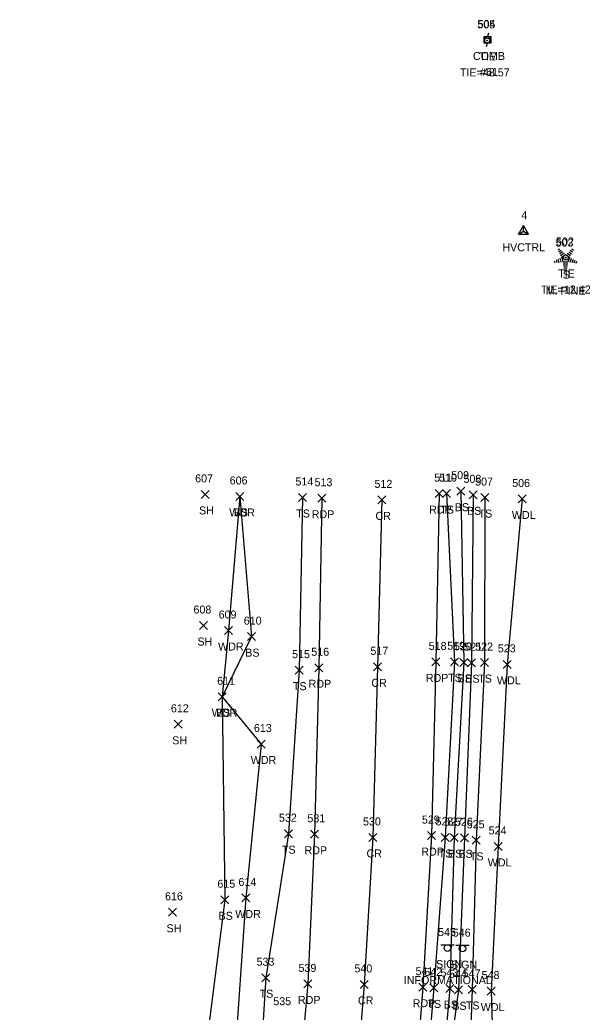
# Model space of a CAD drawing. Extents: x 1638705 to 1644019, y 630225 to 637423.
# Drawn here: x 1643810.7 to 1643953.1, y 637174.9 to 637422.9 of the extents above; entities that cross this region are included whole.
import ezdxf

# ---------------------------------------------------------------- set-up
doc = ezdxf.new("R2010")
doc.units = 0
for name, color, linetype in [('C_A', 7, 'Continuous'), ('C_C', 7, 'Continuous'), ('C_I', 7, 'Continuous'), ('CBP', 7, 'Continuous'), ('CPSM', 7, 'Continuous'), ('L_A', 7, 'Continuous'), ('L_C', 7, 'Continuous'), ('L_I', 7, 'Continuous'), ('L_TIC', 7, 'Continuous'), ('LAWA', 7, 'Continuous'), ('LELB', 7, 'Continuous'), ('LTC', 7, 'Continuous'), ('P_A', 7, 'Continuous'), ('P_I', 7, 'Continuous'), ('P_TIC', 7, 'Continuous'), ('PET', 7, 'Continuous'), ('PRC', 7, 'Continuous'), ('R_I', 7, 'Continuous'), ('S_A', 7, 'Continuous'), ('S_C', 7, 'Continuous'), ('S_I', 7, 'Continuous'), ('SSGN', 7, 'Continuous'), ('U_A', 7, 'Continuous'), ('U_C', 7, 'Continuous'), ('U_I', 7, 'Continuous'), ('UP', 7, 'Continuous')]:
    doc.layers.add(name, color=color, linetype=linetype)

msp = doc.modelspace()

# ---------------------------------------------------------------- linework, layer by layer
at = {"layer": 'CBP'}
for centre, radius in [((1643927.39, 637417.75), 0.625), ((1643927.39, 637417.75), 0.0833), ((1643947.07, 637363.49), 0.625), ((1643947.07, 637363.49), 0.0833)]:
    msp.add_circle(centre, radius, dxfattribs=at)
at = {"layer": 'CPSM'}
for p, q in [((1643935.25, 637369.32), (1643936.5, 637371.48)), ((1643935.25, 637369.32), (1643936.5, 637370.04)), ((1643937.75, 637369.32), (1643936.5, 637371.48)), ((1643936.5, 637370.04), (1643936.5, 637371.48)), ((1643936.5, 637370.04), (1643936.5, 637370.04)), ((1643936.5, 637370.04), (1643937.75, 637369.32)), ((1643935.25, 637369.32), (1643937.75, 637369.32))]:
    msp.add_line(p, q, dxfattribs=at)
at = {"layer": 'L_TIC'}
for points in [[(1643855.95, 637303.28), (1643857.95, 637305.28)], [(1643857.95, 637303.28), (1643855.95, 637305.28)], [(1643916.29, 637303.48), (1643918.29, 637305.48)], [(1643918.29, 637303.48), (1643916.29, 637305.48)], [(1643919.86, 637304.09), (1643921.86, 637306.09)], [(1643921.86, 637304.09), (1643919.86, 637306.09)], [(1643922.94, 637303.18), (1643924.94, 637305.18)], [(1643924.94, 637303.18), (1643922.94, 637305.18)], [(1643864.64, 637302.77), (1643866.64, 637304.77)], [(1643866.64, 637302.77), (1643864.64, 637304.77)], [(1643864.64, 637302.77), (1643866.64, 637304.77)], [(1643866.64, 637302.77), (1643864.64, 637304.77)], [(1643880.31, 637302.51), (1643882.31, 637304.51)], [(1643882.31, 637302.51), (1643880.31, 637304.51)], [(1643925.85, 637302.49), (1643927.85, 637304.49)], [(1643927.85, 637302.49), (1643925.85, 637304.49)], [(1643935.15, 637302.14), (1643937.15, 637304.14)], [(1643937.15, 637302.14), (1643935.15, 637304.14)], [(1643855.53, 637270.51), (1643857.53, 637272.51)], [(1643857.53, 637270.51), (1643855.53, 637272.51)], [(1643861.82, 637269.27), (1643863.82, 637271.27)], [(1643863.82, 637269.27), (1643861.82, 637271.27)], [(1643867.54, 637267.73), (1643869.54, 637269.73)], [(1643869.54, 637267.73), (1643867.54, 637269.73)], [(1643918.24, 637261.47), (1643920.24, 637263.47)], [(1643920.24, 637261.47), (1643918.24, 637263.47)], [(1643920.58, 637261.31), (1643922.58, 637263.31)], [(1643922.58, 637261.31), (1643920.58, 637263.31)], [(1643922.5, 637261.22), (1643924.5, 637263.22)], [(1643924.5, 637261.22), (1643922.5, 637263.22)], [(1643925.79, 637261.26), (1643927.79, 637263.26)], [(1643927.79, 637261.26), (1643925.79, 637263.26)], [(1643931.43, 637260.81), (1643933.43, 637262.81)], [(1643933.43, 637260.81), (1643931.43, 637262.81)], [(1643879.47, 637259.36), (1643881.47, 637261.36)], [(1643881.47, 637259.36), (1643879.47, 637261.36)], [(1643860.25, 637252.7), (1643862.25, 637254.7)], [(1643862.25, 637252.7), (1643860.25, 637254.7)], [(1643860.25, 637252.7), (1643862.25, 637254.7)], [(1643862.25, 637252.7), (1643860.25, 637254.7)], [(1643849.25, 637245.82), (1643851.25, 637247.82)], [(1643851.25, 637245.82), (1643849.25, 637247.82)], [(1643869.99, 637240.9), (1643871.99, 637242.9)], [(1643871.99, 637240.9), (1643869.99, 637242.9)], [(1643876.75, 637218.48), (1643878.75, 637220.48)], [(1643878.75, 637218.48), (1643876.75, 637220.48)], [(1643915.89, 637217.55), (1643917.89, 637219.55)], [(1643917.89, 637217.55), (1643915.89, 637219.55)], [(1643918.17, 637217.5), (1643920.17, 637219.5)], [(1643920.17, 637217.5), (1643918.17, 637219.5)], [(1643920.79, 637217.47), (1643922.79, 637219.47)], [(1643922.79, 637217.47), (1643920.79, 637219.47)], [(1643923.68, 637216.83), (1643925.68, 637218.83)], [(1643925.68, 637216.83), (1643923.68, 637218.83)], [(1643929.14, 637215.31), (1643931.14, 637217.31)], [(1643931.14, 637215.31), (1643929.14, 637217.31)], [(1643860.87, 637201.97), (1643862.87, 637203.97)], [(1643862.87, 637201.97), (1643860.87, 637203.97)], [(1643866.11, 637202.42), (1643868.11, 637204.42)], [(1643868.11, 637202.42), (1643866.11, 637204.42)], [(1643847.83, 637198.85), (1643849.83, 637200.85)], [(1643849.83, 637198.85), (1643847.83, 637200.85)], [(1643871.16, 637182.49), (1643873.16, 637184.49)], [(1643873.16, 637182.49), (1643871.16, 637184.49)], [(1643913.08, 637179.95), (1643915.08, 637181.95)], [(1643915.08, 637179.95), (1643913.08, 637181.95)], [(1643917.1, 637179.78), (1643919.1, 637181.78)], [(1643919.1, 637179.78), (1643917.1, 637181.78)], [(1643919.28, 637179.47), (1643921.28, 637181.47)], [(1643921.28, 637179.47), (1643919.28, 637181.47)], [(1643922.67, 637179.56), (1643924.67, 637181.56)], [(1643924.67, 637179.56), (1643922.67, 637181.56)], [(1643927.39, 637179.15), (1643929.39, 637181.15)], [(1643929.39, 637179.15), (1643927.39, 637181.15)]]:
    msp.add_lwpolyline(points, dxfattribs=at)
at = {"layer": 'LAWA'}
for points in [[(1643865.64, 637303.77), (1643862.82, 637270.27), (1643861.25, 637253.7), (1643870.99, 637241.9), (1643867.11, 637203.42), (1643864.21, 637161.34), (1643862.97, 637130.77), (1643854.22, 637098.04), (1643864.2, 637092.72), (1643858.24, 637074.74), (1643852.38, 637053.09), (1643849.03, 637029.11), (1643850.77, 637013.92), (1643837.37, 636980.48), (1643832.85, 636980.73), (1643828.82, 636965.18), (1643821.8, 636940.41), (1643821.76, 636915.63), (1643813.91, 636882.55), (1643810.67, 636866.31)], [(1643936.15, 637303.14), (1643932.43, 637261.81), (1643930.14, 637216.31), (1643928.39, 637180.15), (1643929.18, 637155.59), (1643934.57, 637122.57), (1643934.09, 637075.7)]]:
    msp.add_lwpolyline(points, dxfattribs=at)
at = {"layer": 'LELB'}
for points in [[(1643920.86, 637305.09), (1643921.58, 637262.31), (1643919.17, 637218.5), (1643918.1, 637180.78), (1643916.28, 637160.37), (1643916.87, 637121.44), (1643917.55, 637101.69), (1643908.97, 637083.26), (1643913.32, 637074.89), (1643911.5, 637058.36), (1643911.28, 637046.38), (1643909.63, 637034.33), (1643911.17, 637020.09), (1643906.37, 637008.31), (1643900.43, 636996.29), (1643899.63, 636992), (1643900.63, 636991.54), (1643901.7, 636994.68), (1643909.42, 637006.82), (1643915.45, 637025.54), (1643915.91, 637032.58), (1643921.31, 637042.59)], [(1643881.31, 637303.51), (1643880.47, 637260.36), (1643877.75, 637219.48), (1643872.16, 637183.49), (1643871.11, 637167.53), (1643875.06, 637139.18), (1643871.64, 637093.85), (1643865.67, 637053.39), (1643855.97, 637011.76), (1643842.4, 636975.8), (1643838.3, 636921.94), (1643830.67, 636893.45), (1643822.68, 636863.82)], [(1643865.64, 637303.77), (1643868.54, 637268.73), (1643861.25, 637253.7), (1643861.87, 637202.97), (1643857, 637164.45), (1643855.35, 637129.62), (1643841.31, 637123.02), (1643837.24, 637109.2), (1643839.09, 637105.62)], [(1643917.29, 637304.48), (1643919.24, 637262.47), (1643916.89, 637218.55), (1643914.08, 637180.95), (1643910.3, 637135.87), (1643913.16, 637114.46), (1643911.21, 637098.67), (1643904.37, 637090.61), (1643898.51, 637049.58), (1643891.41, 637000.85), (1643892.59, 636975.41), (1643882.01, 636960.09), (1643871.05, 636914.88), (1643861.76, 636881.64), (1643855.17, 636855.93)], [(1643923.94, 637304.18), (1643923.5, 637262.22), (1643921.79, 637218.47), (1643920.28, 637180.47), (1643917.61, 637160.93), (1643921.46, 637120.97), (1643921.14, 637098.69), (1643919.98, 637075.96)], [(1643926.85, 637303.49), (1643926.79, 637262.26), (1643924.68, 637217.83), (1643923.67, 637180.56), (1643922.91, 637160.06), (1643931.41, 637125.09), (1643926.6, 637098.61), (1643928.62, 637076.78)]]:
    msp.add_lwpolyline(points, dxfattribs=at)
at = {"layer": 'LTC'}
for p, q in [((1643945.13, 637365.39), (1643945.48, 637365.65)), ((1643945.34, 637364.93), (1643945.87, 637365.31)), ((1643945.55, 637364.46), (1643946.25, 637364.97)), ((1643945.76, 637364), (1643946.63, 637364.63)), ((1643947.41, 637364.59), (1643948.22, 637364)), ((1643947.78, 637364.94), (1643948.46, 637364.44)), ((1643948.15, 637365.29), (1643948.7, 637364.89)), ((1643948.53, 637365.63), (1643948.95, 637365.33)), ((1643944.16, 637362.67), (1643944.31, 637362.21)), ((1643944.62, 637362.89), (1643944.83, 637362.24)), ((1643945.07, 637363.11), (1643945.34, 637362.27)), ((1643945.53, 637363.32), (1643945.86, 637362.3)), ((1643945.98, 637363.54), (1643946.99, 637364.28)), ((1643945.98, 637363.54), (1643946.37, 637362.35)), ((1643947.6, 637362.35), (1643946.37, 637362.35)), ((1643946.99, 637364.28), (1643947.99, 637363.55)), ((1643947.99, 637363.55), (1643947.6, 637362.35)), ((1643948.43, 637363.28), (1643948.09, 637362.24)), ((1643948.87, 637363.03), (1643948.58, 637362.15)), ((1643949.32, 637362.78), (1643949.08, 637362.05)), ((1643949.76, 637362.53), (1643949.57, 637361.96)), ((1643947.56, 637361.85), (1643946.42, 637361.85)), ((1643947.48, 637361.35), (1643946.49, 637361.35)), ((1643947.39, 637360.85), (1643946.56, 637360.85)), ((1643947.31, 637360.35), (1643946.63, 637360.35))]:
    msp.add_line(p, q, dxfattribs=at)
at = {"layer": 'P_TIC'}
for points in [[(1643914.42, 637303.49), (1643916.42, 637305.49)], [(1643916.42, 637303.49), (1643914.42, 637305.49)], [(1643885.09, 637302.33), (1643887.09, 637304.33)], [(1643887.09, 637302.33), (1643885.09, 637304.33)], [(1643900.07, 637301.92), (1643902.07, 637303.92)], [(1643902.07, 637301.92), (1643900.07, 637303.92)], [(1643913.6, 637261.42), (1643915.6, 637263.42)], [(1643915.6, 637261.42), (1643913.6, 637263.42)], [(1643884.33, 637259.95), (1643886.33, 637261.95)], [(1643886.33, 637259.95), (1643884.33, 637261.95)], [(1643899.04, 637260.19), (1643901.04, 637262.19)], [(1643901.04, 637260.19), (1643899.04, 637262.19)], [(1643883.29, 637218.34), (1643885.29, 637220.34)], [(1643885.29, 637218.34), (1643883.29, 637220.34)], [(1643897.85, 637217.55), (1643899.85, 637219.55)], [(1643899.85, 637217.55), (1643897.85, 637219.55)], [(1643912.48, 637218.01), (1643914.48, 637220.01)], [(1643914.48, 637218.01), (1643912.48, 637220.01)], [(1643881.65, 637180.95), (1643883.65, 637182.95)], [(1643883.65, 637180.95), (1643881.65, 637182.95)], [(1643895.7, 637180.82), (1643897.7, 637182.82)], [(1643897.7, 637180.82), (1643895.7, 637182.82)], [(1643910.31, 637180.13), (1643912.31, 637182.13)], [(1643912.31, 637180.13), (1643910.31, 637182.13)]]:
    msp.add_lwpolyline(points, dxfattribs=at)
at = {"layer": 'PET'}
for points in [[(1643886.09, 637303.33), (1643885.33, 637260.95), (1643884.29, 637219.34), (1643882.65, 637181.95), (1643878.66, 637138.56), (1643873.79, 637093.66), (1643868.41, 637053.44), (1643859.66, 637004.66), (1643851.59, 636964.82), (1643841.08, 636921.12), (1643833.58, 636892.49), (1643824.77, 636863.46)], [(1643915.42, 637304.49), (1643914.6, 637262.42), (1643913.48, 637219.01), (1643911.31, 637181.13), (1643907.88, 637136.04), (1643902.19, 637091.19), (1643896.2, 637050.09), (1643887.54, 637001.12), (1643879.88, 636960.46), (1643869.1, 636915.33), (1643860.5, 636882.08), (1643852.88, 636856.28)]]:
    msp.add_lwpolyline(points, dxfattribs=at)
at = {"layer": 'PRC'}
msp.add_lwpolyline([(1643901.07, 637302.92), (1643900.04, 637261.19), (1643898.85, 637218.55), (1643896.7, 637181.82), (1643893.13, 637137.2), (1643887.51, 637091.29), (1643882.08, 637051.36), (1643873.69, 637003.61), (1643865.54, 636962.88), (1643854.81, 636918.08), (1643846.66, 636887.04), (1643838.69, 636859.97)], dxfattribs=at)
at = {"layer": 'SSGN'}
for p, q in [((1643915.88, 637191.75), (1643919.21, 637191.75)), ((1643917.52, 637190.92), (1643917.52, 637190.92)), ((1643919.61, 637191.61), (1643922.94, 637191.61)), ((1643921.25, 637190.78), (1643921.25, 637190.78))]:
    msp.add_line(p, q, dxfattribs=at)
for centre in [(1643917.52, 637190.92), (1643921.25, 637190.78)]:
    msp.add_circle(centre, 0.833, dxfattribs=at)
at = {"layer": 'UP'}
for p, q in [((1643927.72, 637419.52), (1643927.47, 637418.69)), ((1643926.64, 637417.02), (1643926.64, 637418.69)), ((1643926.64, 637418.69), (1643928.3, 637418.69)), ((1643928.3, 637417.02), (1643926.64, 637417.02)), ((1643927.22, 637416.19), (1643927.47, 637417.02)), ((1643927.47, 637417.85), (1643927.47, 637417.85)), ((1643928.3, 637418.69), (1643928.3, 637417.02))]:
    msp.add_line(p, q, dxfattribs=at)
msp.add_circle((1643927.47, 637417.85), 0.833, dxfattribs=at)

# ---------------------------------------------------------------- texts
at = {"layer": 'C_A'}
for s, p in [('TIE', (1643925.47, 637412.75)), ('HVCTRL', (1643931.2, 637365.04)), ('TIE', (1643945.15, 637358.49))]:
    msp.add_text(s, height=2, dxfattribs=at).set_placement(p)
at = {"layer": 'C_C'}
for s, p in [('TIE=48.57', (1643920.62, 637408.75)), ('TIE=12.42', (1643940.86, 637354.49))]:
    msp.add_text(s, height=2, dxfattribs=at).set_placement(p)
at = {"layer": 'C_I'}
for s, p in [('505', (1643924.95, 637420.75)), ('4', (1643935.94, 637373.04)), ('502', (1643944.63, 637366.49))]:
    msp.add_text(s, height=2, dxfattribs=at).set_placement(p)
at = {"layer": 'L_A'}
for s, p in [('S', (1643946.32, 637358.19)), ('SH', (1643855.44, 637299.28)), ('WDR', (1643863, 637298.77)), ('BS', (1643864.08, 637298.77)), ('TS', (1643879.72, 637298.51)), ('TS', (1643915.7, 637299.48)), ('BS', (1643919.31, 637300.09)), ('BS', (1643922.38, 637299.18)), ('TS', (1643925.26, 637298.49)), ('WDL', (1643933.57, 637298.14)), ('SH', (1643855.02, 637266.51)), ('WDR', (1643860.19, 637265.27)), ('BS', (1643866.98, 637263.73)), ('TS', (1643917.65, 637257.47)), ('BS', (1643920.02, 637257.31)), ('BS', (1643921.94, 637257.22)), ('TS', (1643925.2, 637257.26)), ('WDL', (1643929.85, 637256.81)), ('TS', (1643878.88, 637255.36)), ('WDR', (1643858.61, 637248.7)), ('BS', (1643859.69, 637248.7)), ('SH', (1643848.73, 637241.82)), ('WDR', (1643868.35, 637236.9)), ('TS', (1643876.16, 637214.48)), ('TS', (1643915.3, 637213.55)), ('BS', (1643917.61, 637213.5)), ('BS', (1643920.23, 637213.47)), ('TS', (1643923.09, 637212.83)), ('WDL', (1643927.56, 637211.31)), ('BS', (1643860.31, 637197.97)), ('WDR', (1643864.48, 637198.42)), ('SH', (1643847.31, 637194.85)), ('TS', (1643870.57, 637178.49)), ('TS', (1643912.49, 637175.95)), ('BS', (1643916.54, 637175.78)), ('BS', (1643918.72, 637175.47)), ('TS', (1643922.08, 637175.56)), ('WDL', (1643925.81, 637175.15))]:
    msp.add_text(s, height=2, dxfattribs=at).set_placement(p)
at = {"layer": 'L_C'}
msp.add_text('M. PINE', height=2, dxfattribs=at).set_placement((1643942.05, 637354.19))
at = {"layer": 'L_I'}
for s, p in [('503', (1643944.49, 637366.19)), ('509', (1643918.42, 637308.09)), ('607', (1643854.46, 637307.28)), ('606', (1643863.09, 637306.77)), ('606', (1643863.09, 637306.77)), ('514', (1643879.52, 637306.51)), ('510', (1643915.4, 637307.48)), ('508', (1643921.5, 637307.18)), ('507', (1643924.41, 637306.49)), ('506', (1643933.66, 637306.14)), ('608', (1643854.04, 637274.51)), ('609', (1643860.33, 637273.27)), ('610', (1643866.61, 637271.73)), ('515', (1643878.68, 637263.36)), ('519', (1643917.44, 637265.47)), ('520', (1643919.13, 637265.31)), ('521', (1643921.7, 637265.22)), ('522', (1643924.43, 637265.26)), ('523', (1643930.07, 637264.81)), ('611', (1643859.97, 637256.7)), ('611', (1643859.97, 637256.7)), ('612', (1643848.4, 637249.82)), ('613', (1643869.14, 637244.9)), ('532', (1643875.39, 637222.48)), ('528', (1643914.52, 637221.55)), ('527', (1643916.81, 637221.5)), ('526', (1643919.38, 637221.47)), ('525', (1643922.31, 637220.83)), ('524', (1643927.78, 637219.31)), ('614', (1643865.27, 637206.42)), ('615', (1643860.02, 637205.97)), ('616', (1643846.93, 637202.85)), ('533', (1643869.8, 637186.49)), ('542', (1643911.72, 637183.95)), ('543', (1643915.74, 637183.78)), ('544', (1643917.92, 637183.47)), ('547', (1643921.31, 637183.56)), ('548', (1643926.03, 637183.15))]:
    msp.add_text(s, height=2, dxfattribs=at).set_placement(p)
at = {"layer": 'LTC'}
msp.add_text('.', height=1.04, rotation=270, dxfattribs=at).set_placement((1643946.88, 637363.29))
at = {"layer": 'P_A'}
for s, p in [('RDP', (1643883.57, 637298.33)), ('CR', (1643899.5, 637297.92)), ('RDP', (1643912.91, 637299.49)), ('RDP', (1643882.81, 637255.95)), ('CR', (1643898.47, 637256.19)), ('RDP', (1643912.09, 637257.42)), ('RDP', (1643881.78, 637214.34)), ('RDP', (1643910.96, 637214.01)), ('CR', (1643897.28, 637213.55)), ('RDP', (1643880.14, 637176.95)), ('CR', (1643895.13, 637176.82)), ('RDP', (1643908.8, 637176.13))]:
    msp.add_text(s, height=2, dxfattribs=at).set_placement(p)
at = {"layer": 'P_I'}
for s, p in [('513', (1643884.29, 637306.33)), ('512', (1643899.27, 637305.92)), ('511', (1643914.2, 637307.49)), ('516', (1643883.48, 637263.95)), ('517', (1643898.24, 637264.19)), ('518', (1643912.81, 637265.42)), ('531', (1643882.5, 637222.34)), ('530', (1643896.4, 637221.55)), ('529', (1643911.11, 637222.01)), ('539', (1643880.28, 637184.95)), ('540', (1643894.25, 637184.82)), ('541', (1643909.51, 637184.13))]:
    msp.add_text(s, height=2, dxfattribs=at).set_placement(p)
at = {"layer": 'R_I'}
msp.add_text('535', height=2, dxfattribs=at).set_placement((1643873.99, 637176.62))
at = {"layer": 'S_A'}
for p in [(1643914.66, 637185.9), (1643918.39, 637185.76)]:
    msp.add_text('SIGN', height=2, dxfattribs=at).set_placement(p)
at = {"layer": 'S_C'}
msp.add_text('INFORMATIONAL', height=2, dxfattribs=at).set_placement((1643906.59, 637181.9))
at = {"layer": 'S_I'}
for s, p in [('545', (1643915.14, 637193.9)), ('546', (1643918.82, 637193.76))]:
    msp.add_text(s, height=2, dxfattribs=at).set_placement(p)
at = {"layer": 'U_A'}
msp.add_text('COMB', height=2, dxfattribs=at).set_placement((1643923.86, 637412.85))
at = {"layer": 'U_C'}
msp.add_text('#61', height=2, dxfattribs=at).set_placement((1643925.63, 637408.85))
at = {"layer": 'U_I'}
msp.add_text('504', height=2, dxfattribs=at).set_placement((1643925.03, 637420.85))

doc.saveas('drawing.dxf')
